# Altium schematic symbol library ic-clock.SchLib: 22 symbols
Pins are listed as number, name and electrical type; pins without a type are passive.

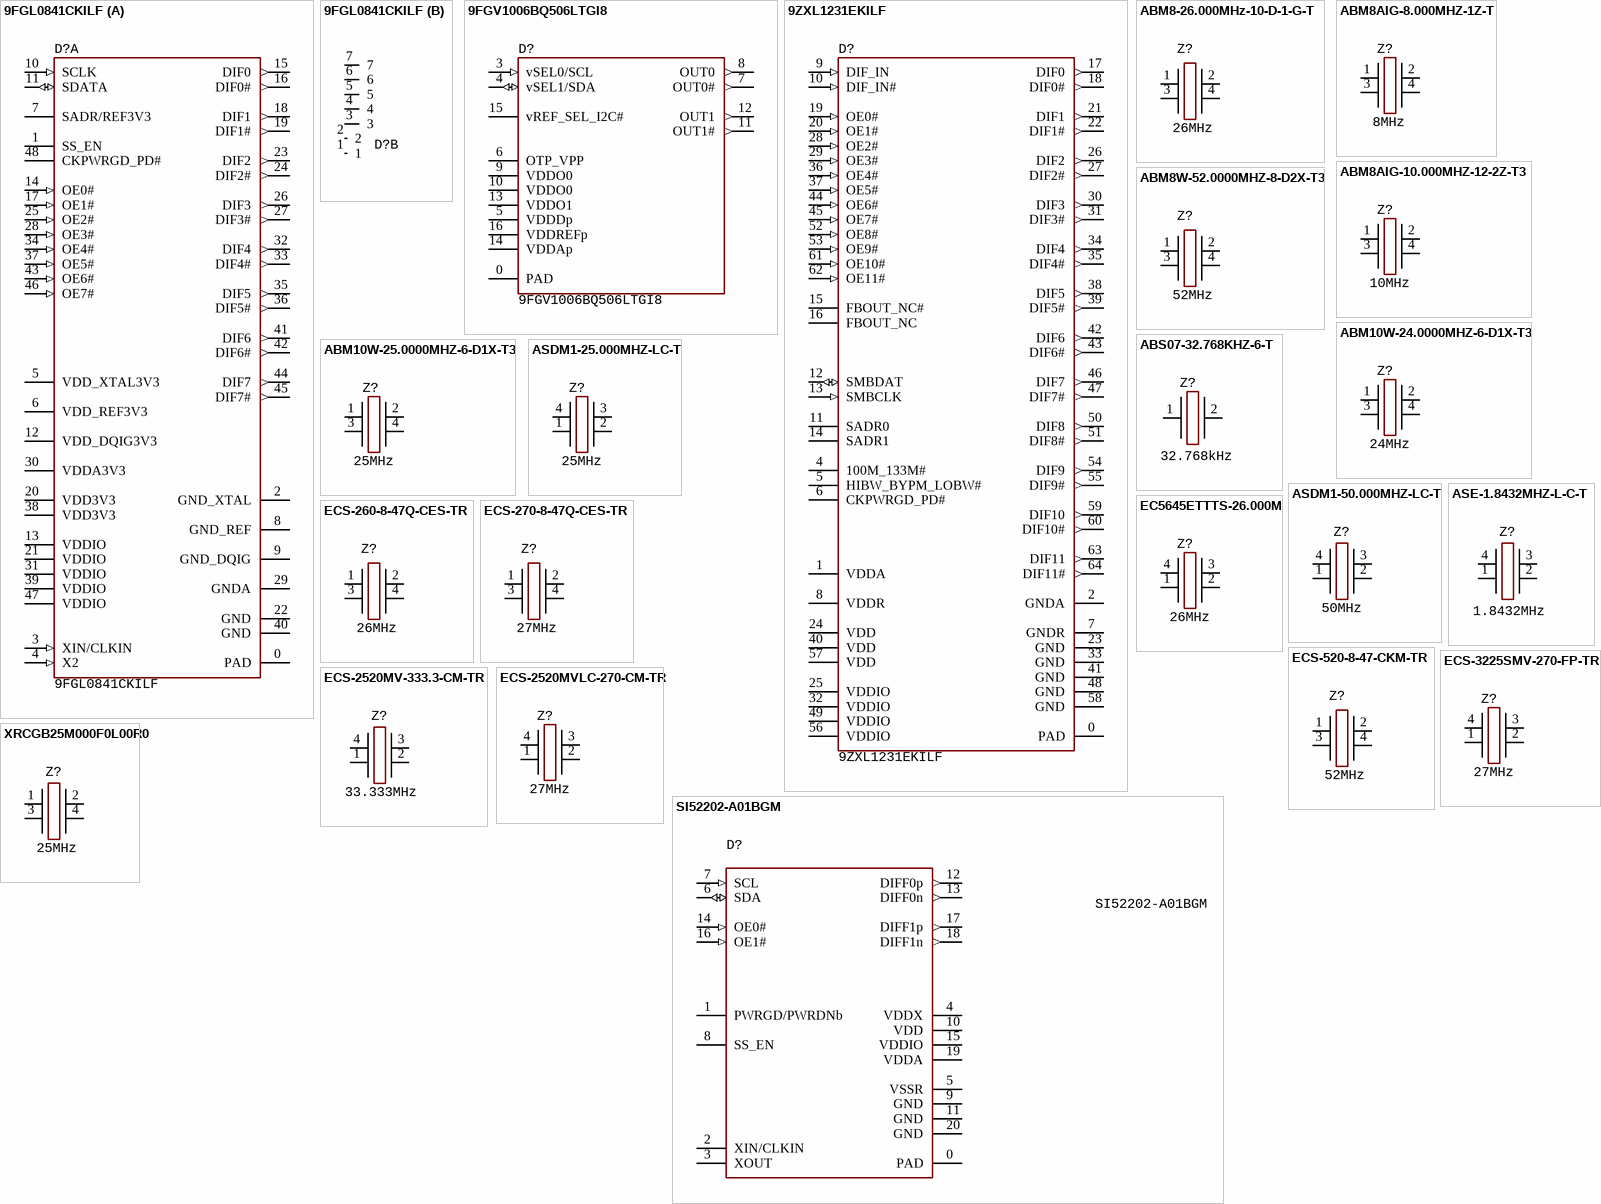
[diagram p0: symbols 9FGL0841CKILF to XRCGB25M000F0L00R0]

## 9FGL0841CKILF
designator D?
Clock Generator, 40 MHz max , 8 output, 50 ps, QFN-48, 3.135...3.465V, -40...+85°C; Manufacturer: Renesans; Manufacturer: Renesas
footprint 48-QFN (6x6, pitch 0.4) (6x6 mm, pitch 0.4 mm, power pad)
part A pins: 0 PAD, 1 SS_EN, 2 GND_XTAL, 3 XIN/CLKIN (in), 4 X2 (in), 5 VDD_XTAL3V3, 6 VDD_REF3V3, 7 SADR/REF3V3, 8 GND_REF, 9 GND_DQIG, 10 SCLK (in), 11 SDATA (io), 12 VDD_DQIG3V3, 13 VDDIO, 14 OE0# (in), 15 DIF0 (out), 16 DIF0# (out), 17 OE1# (in), 18 DIF1 (out), 19 DIF1# (out), 20 VDD3V3, 21 VDDIO, 22 GND, 23 DIF2 (out), 24 DIF2# (out), 25 OE2# (in), 26 DIF3 (out), 27 DIF3# (out), 28 OE3# (in), 29 GNDA, 30 VDDA3V3, 31 VDDIO, 32 DIF4 (out), 33 DIF4# (out), 34 OE4# (in), 35 DIF5 (out), 36 DIF5# (out), 37 OE5# (in), 38 VDD3V3, 39 VDDIO, 40 GND, 41 DIF6 (out), 42 DIF6# (out), 43 OE6# (in), 44 DIF7 (out), 45 DIF7# (out), 46 OE7# (in), 47 VDDIO, 48 CKPWRGD_PD#
part B pins: 1, 2, 3, 4, 5, 6, 7

## 9FGV1006BQ506LTGI8
designator D?
Clock Generator, 100 MHz, 2 output, 276 fs, LGA-16, 1.71...3.465V, -40...+85°C; Manufacturer: Renesans; Manufacturer: Renesas
footprint 16-LGA (3x3) (3x3 mm, pitch 0.5 mm)
pins: 0 PAD, 3 vSEL0/SCL (in), 4 vSEL1/SDA (io), 5 VDDDp, 6 OTP_VPP, 7 OUT0# (out), 8 OUT0 (out), 9 VDDO0, 10 VDDO0, 11 OUT1# (out), 12 OUT1 (out), 13 VDDO1, 14 VDDAp, 15 vREF_SEL_I2C#, 16 VDDREFp

## 9ZXL1231EKILF
designator D?
Clock Buffer, 150 MHz, 12 output, 40 fs, QFN-64, 3.135...3.465V, -40...+85°C; Manufacturer: Renesans; Manufacturer: IDT
footprint 64-QFN (9x9, pitch 0.5) (9x9 mm, pitch 0.5 mm, power pad)
pins: 0 PAD, 1 VDDA, 2 GNDA, 4 100M_133M#, 5 HIBW_BYPM_LOBW#, 6 CKPWRGD_PD#, 7 GNDR, 8 VDDR, 9 DIF_IN (in), 10 DIF_IN# (in), 11 SADR0, 12 SMBDAT (io), 13 SMBCLK (in), 14 SADR1, 15 FBOUT_NC#, 16 FBOUT_NC, 17 DIF0 (out), 18 DIF0# (out), 19 OE0# (in), 20 OE1# (in), 21 DIF1 (out), 22 DIF1# (out), 23 GND, 24 VDD, 25 VDDIO, 26 DIF2 (out), 27 DIF2# (out), 28 OE2# (in), 29 OE3# (in), 30 DIF3 (out), 31 DIF3# (out), 32 VDDIO, 33 GND, 34 DIF4 (out), 35 DIF4# (out), 36 OE4# (in), 37 OE5# (in), 38 DIF5 (out), 39 DIF5# (out), 40 VDD, 41 GND, 42 DIF6 (out), 43 DIF6# (out), 44 OE6# (in), 45 OE7# (in), 46 DIF7 (out), 47 DIF7# (out), 48 GND, 49 VDDIO, 50 DIF8 (out), 51 DIF8# (out), 52 OE8# (in), 53 OE9# (in), 54 DIF9 (out), 55 DIF9# (out), 56 VDDIO, 57 VDD, 58 GND, 59 DIF10 (out), 60 DIF10# (out), 61 OE10# (in), 62 OE11# (in), 63 DIF11 (out), 64 DIF11# (out)

## ABM8-26.000MHz-10-D-1-G-T
designator Z?, comment 26MHz
Crystal, 26 MHz, 10pF, case 3225, ±15ppm, -40...+125°C; PartNumber: ABM8-26.000MHz-10-D-1-G-T; Manufacturer: Abracon
footprint OSC: 3225
pins: 1, 2, 3, 4

## ABM8AIG-8.000MHZ-1Z-T
designator Z?, comment 8MHz
Crystal, 8 MHz, 18pF, case 3225, ±25ppm, -40...+125°C; PartNumber: ABM8AIG-8.000MHZ-1Z-T; Manufacturer: Abracon
footprint OSC: 3225
pins: 1, 2, 3, 4

## ABM8AIG-10.000MHZ-12-2Z-T3
designator Z?, comment 10MHz
Crystal, 10 MHz, 12pF, case 3225, ±25ppm, -40...+125°C; PartNumber: ABM8AIG-10.000MHZ-12-2Z-T3; Manufacturer: Abracon
footprint OSC: 3225
pins: 1, 2, 3, 4

## ABM8W-52.0000MHZ-8-D2X-T3
designator Z?, comment 52MHz
Crystal, 52 MHz, 8pF, case 3225, ±10ppm, -20...+70°C; PartNumber: ABM8W-52.0000MHZ-8-D2X-T3; Manufacturer: Abracon
footprint OSC: 3225
pins: 1, 2, 3, 4

## ABM10W-24.0000MHZ-6-D1X-T3
designator Z?, comment 24MHz
Crystal, 24 MHz, 6pF, case 2520, ±50ppm, -40...+85°C; PartNumber: ABM10W-24.0000MHZ-6-D1X-T3; Manufacturer: Abracon
footprint OSC: 2520
pins: 1, 2, 3, 4

## ABM10W-25.0000MHZ-6-D1X-T3
designator Z?, comment 25MHz
Crystal, 25 MHz, 6pF, case 2520, ±50ppm, -40...+85°C; Manufacturer: Abracon; PartNumber: ABM10W-25.0000MHZ-6-D1X-T3
footprint OSC: 2520
pins: 1, 2, 3, 4

## ABS07-32.768KHZ-6-T
designator Z?, comment 32.768kHz
Crystal, 32.768 kHz, 6pF, case 3215, ±20ppm, -40...+85°C; PartNumber: ABS07-32.768KHZ-6-T; Manufacturer: Abracon
footprint OSC: 3215
pins: 1, 2

## ASDM1-25.000MHZ-LC-T
designator Z?, comment 25MHz
Oscillator, 25MHz, ±50ppm, case 2520, supply 1.8...3.3V, -40...+70°C; PartNumber: ASDM1-25.000MHZ-LC-T; Manufacturer: Abracon LLC
footprint OSC: 2520
pins: 1, 2, 3, 4

## ASDM1-50.000MHZ-LC-T
designator Z?, comment 50MHz
Oscillator, 50 MHz, supply 1.8...3.3V, case 2520, ±50ppm, -40...+85°C; Manufacturer: Abracon; PartNumber: ASDM1-50.000MHZ-LC-T
footprint OSC: 2520
pins: 1, 2, 3, 4

## ASE-1.8432MHZ-L-C-T
designator Z?, comment 1.8432MHz
Oscillator, 1.8432MHz, ±50ppm, case 3225, supply 3.135...3.465V, -40...+85°C; PartNumber: ASE-1.8432MHZ-L-C-T; Manufacturer: Abracon LLC
footprint OSC: 3225
pins: 1, 2, 3, 4

## EC5645ETTTS-26.000M
designator Z?, comment 26MHz
Oscillator, 26MHz, ±50ppm, case 2520, supply 2.97...3.63V, -40...+85EC5645ETTTS-26.000M°C; Manufacturer: Abracon
footprint OSC: 2520
pins: 1, 2, 3, 4

## ECS-260-8-47Q-CES-TR
designator Z?, comment 26MHz
Crystal, 26 MHz, 8pF, case 1612, ±50ppm, -40...+125°C; PartNumber: ECS-260-8-47Q-CES-TR; Manufacturer: ECS
footprint OSC: 1612
pins: 1, 2, 3, 4

## ECS-270-8-47Q-CES-TR
designator Z?, comment 27MHz
Crystal, 27 MHz, 8pF, case 1612, ±50ppm, -40...+125°C; PartNumber: ECS-270-8-47Q-CES-TR; Manufacturer: ECS
footprint OSC: 1612
pins: 1, 2, 3, 4

## ECS-520-8-47-CKM-TR
designator Z?, comment 52MHz
Crystal, 52 MHz, 10pF, case 1612, ±10ppm, -20...+70°C; PartNumber: ECS-520-8-47-CKM-TR; Manufacturer: ECS
footprint OSC: 1612
pins: 1, 2, 3, 4

## ECS-2520MV-333.3-CM-TR
designator Z?, comment 33.333MHz
Oscillator, 33.333 MHz, supply 1.6...3.6V, case 2520, ±50ppm, -20...+70°C; Manufacturer: ECS; PartNumber: ECS-2520MV-333.3-CM-TR
footprint OSC: 2520
pins: 1, 2, 3, 4

## ECS-2520MVLC-270-CM-TR
designator Z?, comment 27MHz
Oscillator, 27MHz, ±25ppm, case 2520, supply 1.6...3.6V, -20...+70°C; PartNumber: ECS-2520MVLC-270-CM-TR; Manufacturer: ECS
footprint OSC: 2520
pins: 1, 2, 3, 4

## ECS-3225SMV-270-FP-TR
designator Z?, comment 27MHz
Oscillator, 27MHz, ±25ppm, case 3225, supply 1.6...3.6V, -20...+70°C; PartNumber: ECS-3225SMV-270-FP-TR; Manufacturer: ECS
footprint OSC: 3225
pins: 1, 2, 3, 4

## SI52202-A01BGM
designator D?
Clock Generator, PCIe Gen 5, 100 Ohms, 25 MHz, supply 1.71...1.89V, -40...+85°C; Manufacturer: Skyworks
footprint 20-QFN (3x3, pitch 0.4 mm) (3x3 mm, pitch 0.4 mm)
pins: 0 PAD, 1 PWRGD/PWRDNb, 2 XIN/CLKIN, 3 XOUT, 4 VDDX, 5 VSSR, 6 SDA (io), 7 SCL (in), 8 SS_EN, 9 GND, 10 VDD, 11 GND, 12 DIFF0p (out), 13 DIFF0n (out), 14 OE0# (in), 15 VDDIO, 16 OE1# (in), 17 DIFF1p (out), 18 DIFF1n (out), 19 VDDA, 20 GND

## XRCGB25M000F0L00R0
designator Z?, comment 25MHz
Crystal, 25 MHz, 6pF, case 2016, ±50ppm, -30...+85°C; PartNumber: XRCGB25M000F0L00R0; Manufacturer: Murata Electronics
footprint OSC: 2016
pins: 1, 2, 3, 4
